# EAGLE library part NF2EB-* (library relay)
FLATPACK RELAY NAiS Source: http://www.mew-europe.com/.. en_ds_61014_0000.pdf
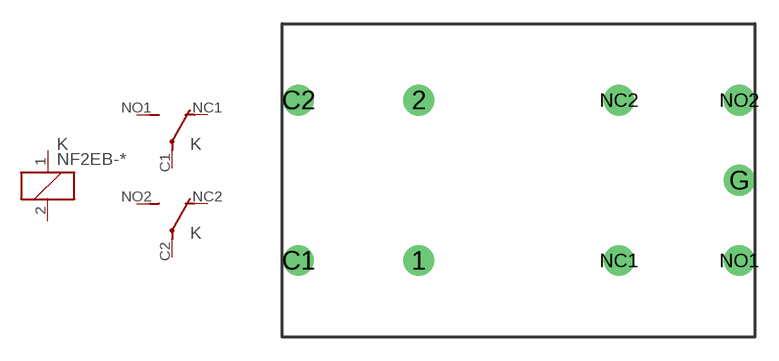
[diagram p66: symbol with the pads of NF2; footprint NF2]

Designator prefix K; gates _=K G$1=U G$2=U

## NF2EB-5V (MPN: NF2EB-5V; OC_FARNELL: 1703747; OC_NEWARK: 13P5538), NF2EB-6V (MPN: NF2EB-6V; OC_FARNELL: unknown; OC_NEWARK: 13P5539), NF2EB-12V (MPN: NF2EB-12V; OC_FARNELL: 1200946; OC_NEWARK: 13P5536), NF2EB-24V (MPN: NF2EB-24V; OC_FARNELL: 1175714; OC_NEWARK: 13P5537), NF2EB-48V (OC_FARNELL: unknown; OC_NEWARK: unknown)  [NF2]
1  _:1  pas
2  _:2  pas
C1  G$1:P  pas
C2  G$2:P  pas
NC1  G$1:O  pas
NC2  G$2:O  pas
NO1  G$1:S  pas
NO2  G$2:S  pas

## Footprint NF2 (pad centres in mm)
FLATPACK RELAY NAiS Source: http://www.mew-europe.com/.. en_ds_61014_0000.pdf
drill 1.3 round: 1 -6.35,-5.08; 2 -6.35,5.08; C1 -13.97,-5.08; C2 -13.97,5.08; G 13.97,0; NC1 6.35,-5.08; NC2 6.35,5.08; NO1 13.97,-5.08; NO2 13.97,5.08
